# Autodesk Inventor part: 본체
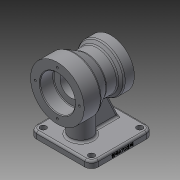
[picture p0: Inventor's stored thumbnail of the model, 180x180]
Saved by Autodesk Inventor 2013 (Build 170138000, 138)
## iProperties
Created: 2019-01
Part Number: 본체
Material: 일반
Document SubType Name: Modeling
Designer: hana-cad23
Density: 1 g/cm^3
Author: hana-cad23
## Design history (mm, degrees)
sketch "스케치1"
  geometry: L1 (-40, 0)-(40, 0); L2 (40, 0)-(40, 35); L3 (40, 35)-(25, 35); L4 (-40, 0)-(-40, 40); L5 (-40, 40)-(-15, 40); L6 (-15, 40)-(3.394, 29.38); L7 (3.394, 29.38)-(20.284, 29.38); L8 (20.284, 29.38)-(25, 35); 2 further points
  constraints: 16 end point, 3 perpendicular, 1 coincident, 1 horizontal, 1 midpoint, 1 parallel
  dimensions: "d0" = 80 distance of L1.start L1.end; "d11" = 15 distance of L2.end L3.end; "d13" = 25 distance of L4.end L5.end; "d14" = 30 deg angle of L5 L6; "d15" = 50 deg angle of L7 L8; "d16" = 80 diameter of L5 L1; "d18" = 70 diameter of L3 L1; "d19" = 16.89004 distance of L6.end L7.end
revolve "회전1" sketch "스케치1" stored, may be unused: angle "d20" = 90 deg
sketch "스케치2"
  geometry: L1 (-40, 35)-(-40, -35) reference; L2 (40, 40)-(40, -40) reference; L3 (40, 0)-(-40, 0); L4 (40, 0)-(40, 26); L5 (40, 26)-(21, 26); L6 (20, 25)-(20, 16); L7 (20, 16)-(-23, 16); L8 (-23, 16)-(-23, 19.4); L9 (-23.6, 20)-(-40, 20); L10 (-40, 20)-(-40, 0); A1 r 1 centre (21, 25) between (21, 26) and (20, 25); A2 r 0.6 centre (-23.6, 19.4) between (-23, 19.4) and (-23.6, 20); 3 further points
  constraints: 16 end point, 6 point on line, 4 point on circle, 4 tangent, 3 perpendicular, 2 centre point, 2 midpoint, 2 parallel, 1 collinear
  dimensions: "d21" = 26 distance of L3.start L4.end; "d22" = 20 distance of L4.end point (20, 26); "d23" = 10 distance of point (20, 26) L6.end; "d24" = 43 distance of L6.end L7.end; "d25" = 4 distance of L7.end point (-23, 20); "d26" = 1 radius of A1; "d27" = 0.6 radius of A2
revolve "회전2" sketch "스케치2" stored, may be unused: angle "d28" = 90 deg
node "작업 평면1"
sketch "스케치3"
  geometry: L1 (-40, -40)-(-40, 40) reference; L2 (-35, -46)-(57, -46); L3 (57, -46)-(57, 46); L4 (57, 46)-(-35, 46); L5 (-35, 46)-(-35, -46); L6 (-35, -46)-(57, 46); L7 (57, -46)-(-35, 46); 4 further points
  constraints: 12 end point, 4 midpoint, 2 parallel, 1 horizontal, 1 horizontal alignment, 1 perpendicular
  dimensions: "d33" = 92 distance of L3.end L4.end; "d35" = 92 distance of L2.end L3.end; "d36" = 5 distance between parallel lines of L1 L5
extrude "돌출1" join sketch "스케치3" distance "d37" = 10; taper "d38" = 0 deg
sketch "스케치4"
  geometry: L1 (35, -46)-(35, 46) reference; C1 r 16 at (5, 0); 2 further points
  constraints: 1 centre point, 1 horizontal alignment, 1 midpoint
  dimensions: "d39" = 32 diameter of C1; "d41" = 30 distance from line of L1 C1.centre
extrude "돌출2" join sketch "스케치4" stored distance "d42" = 10; taper "d43" = 0 deg
sketch "스케치5"
  geometry: L1 (-57, 80)-(-57, 70) reference; L2 (-47, 70)-(-26.137, 25.258); L3 (35, 70)-(-57, 70) reference; L4 (-47, 70)-(-6.839, 70); L5 (-6.839, 25.258)-(-26.137, 25.258); L6 (-6.839, 70)-(-6.839, 25.258); 1 further point
  constraints: 8 end point, 1 parallel, 1 perpendicular, 1 point on line
  dimensions: "d45" = 25 deg angle of L1 L2; "d46" = 10 distance from line of L1 L2.start; "d47" = 40.161 distance of L2.start L4.end; "d48" = 44.74174 distance of L4.end L5.start; "d49" = 19.29758 distance of L5.start L2.end
extrude "돌출3" join sketch "스케치5" stored distance "d50" = 10; taper "d51" = 0 deg
fillet "모깎기1" dims "d52" = 10
sketch "스케치6"
  geometry: C1 r 4.5 at (-47, 36); C2 r 4.5 at (-47, -36); C3 r 4.5 at (25, 36); C4 r 4.5 at (25, -36); A1 r 10 centre (25, 36) between (35, 36) and (25, 46) reference; A2 r 10 centre (-47, 36) between (-47, 46) and (-57, 36) reference; A3 r 10 centre (-47, -36) between (-57, -36) and (-47, -46) reference; A4 r 10 centre (25, -36) between (25, -46) and (35, -36) reference; 1 further point
  constraints: 4 centre point, 4 coincident
  dimensions: "d53" = 9 diameter of C1; "d54" = 9 diameter of C2; "d55" = 9 diameter of C3; "d56" = 9 diameter of C4
extrude "돌출4" cut sketch "스케치6" stored distance "d57" = 10; taper "d58" = 0 deg
fillet "모깎기2" dims "d59" = 3
fillet "모깎기3" dims "d60" = 3
fillet "모깎기4" dims "d61" = 3
sketch "스케치7"
  geometry: C1 r 26 at (0, 0) reference; 1 further point
  constraints: 1 vertical alignment
  dimensions: "d62" = 33 distance of C1.centre point (0, -33)
hole "구멍1" sketch "스케치7" at (0, -33) diameter "d63" = 3.242; stored, may be unused: countersink angle "d67" = 90 deg, drill point angle "d69" = 118 deg; dims "d64" = 9, "d65" = 4, "d66" = 2, "d68" = 11
sketch "스케치8"
  geometry: C1 r 20 at (0, 0) reference; 1 further point
  constraints: 1 vertical alignment
  dimensions: "d73" = 27.5 distance of point (0, -27.5) C1.centre
hole "구멍2" sketch "스케치8" at (0, -27.5) diameter "d74" = 3.242; stored, may be unused: countersink angle "d78" = 90 deg, drill point angle "d80" = 118 deg; dims "d75" = 9, "d76" = 4, "d77" = 2, "d79" = 11
chamfer "모따기1" distance "d84" = 1; stored, may be unused: second distance "d85" = 2, angle "d86" = 45 deg
node "작업 평면2"
sketch "스케치9"
  geometry: L1 (35, 73)-(35, 80) reference; L2 (-47, 80)-(25, 80) reference; L3 (-57, 80)-(-47, 80) reference; 2 further points
  constraints: 1 other
  dimensions: "d88" = 46 distance from line of point (-11, 76) L1; "d89" = 4 distance from line of L3 point (-11, 76)
feature "엠보싱1" sketch "스케치9" dims "d0" = 80, "d11" = 15, "d13" = 25, "d14" = 30 deg, "d15" = 50 deg, "d16" = 80, "d18" = 70, "d19" = 16.89004, "d90" = 0.5, "d91" = 0
node "솔리드1"
pattern_circular "원형 패턴1" dims angle "d71" = 360 deg
pattern_circular "원형 패턴2" dims angle "d82" = 360 deg
other parameters: "d87" = 62.5
